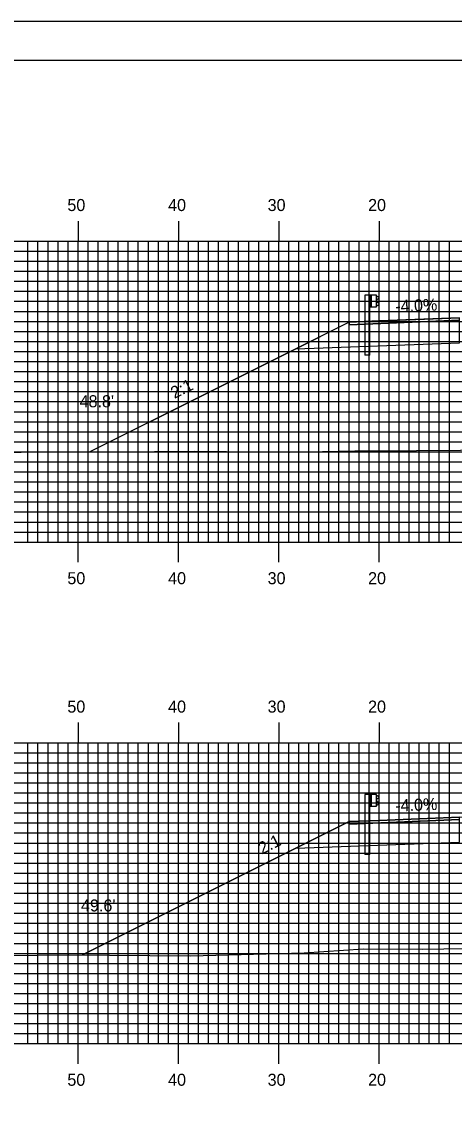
# Model space of a CAD drawing. Extents: x 1761004 to 1761347, y 442591 to 442811.
# Drawn here: x 1761114.1 to 1761157.2, y 442702.5 to 442810.5 of the extents above; entities that cross this region are included whole.
import ezdxf

# ---------------------------------------------------------------- set-up
doc = ezdxf.new("R2010")
doc.units = 0
for name, color, linetype in [('ANNOTATION', 7, 'Continuous'), ('BORDER', 7, 'Continuous'), ('D_Guardrail_Beam_Lt', 7, 'Continuous'), ('D_Roadway_Centerline', 7, 'Continuous'), ('D_Roadway_Edge_Shoulder', 7, 'Continuous'), ('D_Roadway_SlopeLines', 7, 'Continuous'), ('D_Roadway_SubGrade', 7, 'Continuous'), ('D_Text_Standard', 7, 'Continuous'), ('H_V ANNOTATION', 7, 'Continuous'), ('MAJOR', 7, 'Continuous'), ('MINOR', 7, 'Continuous'), ('PLOT BOUNDARY', 7, 'Continuous'), ('S_Roadway_Centerline', 7, 'Continuous')]:
    doc.layers.add(name, color=color, linetype=linetype)

msp = doc.modelspace()

# ---------------------------------------------------------------- linework, layer by layer
at = {"layer": 'BORDER'}
msp.add_lwpolyline([(1761020.13, 442596.67), (1761340.13, 442596.67), (1761340.13, 442806.67), (1761020.13, 442806.67)], close=True, dxfattribs=at)
at = {"layer": 'D_Guardrail_Beam_Lt'}
for p, q in [((1761148.3, 442783.3), (1761148.3, 442777.3)), ((1761148.77, 442783.3), (1761148.3, 442783.3)), ((1761149.46, 442783.3), (1761148.77, 442783.3)), ((1761148.77, 442783.3), (1761148.77, 442782.13)), ((1761148.83, 442783.3), (1761148.83, 442782.13)), ((1761148.94, 442783.3), (1761148.94, 442782.13)), ((1761149.46, 442782.13), (1761149.46, 442783.3)), ((1761149.46, 442783.21), (1761149.53, 442783.2)), ((1761149.46, 442782.75), (1761149.46, 442782.68)), ((1761149.69, 442782.95), (1761149.49, 442782.81)), ((1761149.49, 442782.61), (1761149.69, 442782.48)), ((1761149.55, 442783.19), (1761149.69, 442783.09)), ((1761148.77, 442782.13), (1761149.46, 442782.13)), ((1761148.79, 442777.3), (1761148.79, 442782.13)), ((1761149.53, 442782.23), (1761149.46, 442782.21)), ((1761149.69, 442782.33), (1761149.55, 442782.23)), ((1761148.79, 442777.3), (1761148.3, 442777.3)), ((1761148.3, 442733.52), (1761148.3, 442727.52)), ((1761148.77, 442733.52), (1761148.3, 442733.52)), ((1761149.46, 442733.52), (1761148.77, 442733.52)), ((1761148.77, 442733.52), (1761148.77, 442732.35)), ((1761148.83, 442733.52), (1761148.83, 442732.35)), ((1761148.94, 442733.52), (1761148.94, 442732.35)), ((1761149.46, 442732.35), (1761149.46, 442733.52)), ((1761149.46, 442733.43), (1761149.53, 442733.42)), ((1761149.46, 442732.97), (1761149.46, 442732.9)), ((1761149.69, 442733.17), (1761149.49, 442733.03)), ((1761149.49, 442732.83), (1761149.69, 442732.7)), ((1761149.55, 442733.41), (1761149.69, 442733.31)), ((1761148.77, 442732.35), (1761149.46, 442732.35)), ((1761148.79, 442727.52), (1761148.79, 442732.35)), ((1761149.53, 442732.45), (1761149.46, 442732.43)), ((1761149.69, 442732.55), (1761149.55, 442732.45)), ((1761148.79, 442727.52), (1761148.3, 442727.52))]:
    msp.add_line(p, q, dxfattribs=at)
for centre, major_axis, start_param, end_param in [((1761149.54, 442782.75), (-0.0789, 0), 5.323254, 6.283185), ((1761149.54, 442782.68), (-0.0789, 0), 6.283185, 7.243116), ((1761149.52, 442783.16), (0.0417, 0), 0.959931, 1.376053), ((1761149.64, 442783.02), (0.0877, 0), 5.323254, 7.243116), ((1761149.52, 442782.27), (0.0417, 0), 4.907132, 5.323254), ((1761149.64, 442782.41), (0.0877, 0), 5.323254, 7.243116), ((1761149.54, 442732.97), (-0.0789, 0), 5.323254, 6.283185), ((1761149.54, 442732.9), (-0.0789, 0), 6.283185, 7.243116), ((1761149.52, 442733.38), (0.0417, 0), 0.959931, 1.376053), ((1761149.64, 442733.24), (0.0877, 0), 5.323254, 7.243116), ((1761149.52, 442732.49), (0.0417, 0), 4.907132, 5.323254), ((1761149.64, 442732.63), (0.0877, 0), 5.323254, 7.243116)]:
    msp.add_ellipse(centre, major_axis=major_axis, ratio=0.995501, start_param=start_param, end_param=end_param, dxfattribs=at)
at = {"layer": 'D_Roadway_Centerline'}
for points in [[(1761120.9, 442767.68), (1761120.94, 442767.7), (1761132.33, 442773.39), (1761141.43, 442777.94), (1761141.43, 442777.95), (1761141.44, 442777.95), (1761146.45, 442780.45), (1761146.73, 442780.59), (1761149.73, 442780.71), (1761153.4, 442780.86), (1761157.73, 442781.03)], [(1761120.16, 442717.53), (1761133.13, 442724.02), (1761141.43, 442728.17), (1761146.73, 442730.81), (1761146.74, 442730.81), (1761149.72, 442730.93), (1761149.73, 442730.93), (1761157.72, 442731.25), (1761157.73, 442731.25), (1761166.12, 442731.56), (1761169.73, 442731.69), (1761175.62, 442731.9), (1761181.72, 442732.12), (1761181.73, 442732.12), (1761181.73, 442732.12), (1761185.69, 442731.96), (1761189.73, 442731.8), (1761192.73, 442731.68), (1761196.28, 442729.9), (1761197.48, 442729.3), (1761197.48, 442729.3), (1761202.44, 442726.82), (1761219.6, 442718.24)]]:
    msp.add_lwpolyline(points, dxfattribs=at)
at = {"layer": 'D_Roadway_Edge_Shoulder'}
for points in [[(1761157.73, 442781.03), (1761149.73, 442780.71), (1761149.73, 442780.71), (1761146.73, 442780.59), (1761146.73, 442780.34), (1761157.73, 442780.78)], [(1761157.73, 442731.25), (1761149.73, 442730.93), (1761149.73, 442730.93), (1761146.73, 442730.81), (1761146.73, 442730.56), (1761157.73, 442731)]]:
    msp.add_lwpolyline(points, close=True, dxfattribs=at)
at = {"layer": 'D_Roadway_SlopeLines'}
for points in [[(1761146.73, 442780.59), (1761120.9, 442767.68)], [(1761146.73, 442730.81), (1761120.16, 442717.53)]]:
    msp.add_lwpolyline(points, dxfattribs=at)
at = {"layer": 'D_Roadway_SubGrade'}
for points in [[(1761157.73, 442780.37), (1761157.73, 442780.78), (1761146.73, 442780.34), (1761146.73, 442780.59), (1761141.43, 442777.95), (1761157.73, 442778.53)], [(1761157.73, 442730.59), (1761157.73, 442731), (1761146.73, 442730.56), (1761146.73, 442730.81), (1761141.43, 442728.17), (1761157.73, 442728.75)]]:
    msp.add_lwpolyline(points, close=True, dxfattribs=at)
at = {"layer": 'MAJOR'}
for p, q in [((1761119.73, 442790.67), (1761119.73, 442788.67)), ((1761129.73, 442790.67), (1761129.73, 442788.67)), ((1761139.73, 442790.67), (1761139.73, 442788.67)), ((1761149.73, 442790.67), (1761149.73, 442788.67)), ((1761029.73, 442788.67), (1761309.73, 442788.67)), ((1761029.73, 442788.67), (1761309.73, 442788.67)), ((1761119.73, 442758.67), (1761119.73, 442788.67)), ((1761129.73, 442758.67), (1761129.73, 442788.67)), ((1761139.73, 442758.67), (1761139.73, 442788.67)), ((1761149.73, 442758.67), (1761149.73, 442788.67)), ((1761029.73, 442783.67), (1761309.73, 442783.67)), ((1761029.73, 442778.67), (1761309.73, 442778.67)), ((1761029.73, 442773.67), (1761309.73, 442773.67)), ((1761029.73, 442768.67), (1761309.73, 442768.67)), ((1761029.73, 442763.67), (1761309.73, 442763.67)), ((1761029.73, 442758.67), (1761309.73, 442758.67)), ((1761029.73, 442758.67), (1761309.73, 442758.67)), ((1761119.73, 442756.66), (1761119.73, 442758.67)), ((1761129.73, 442756.66), (1761129.73, 442758.67)), ((1761139.73, 442756.66), (1761139.73, 442758.67)), ((1761149.73, 442756.66), (1761149.73, 442758.67)), ((1761119.73, 442740.67), (1761119.73, 442738.67)), ((1761129.73, 442740.67), (1761129.73, 442738.67)), ((1761139.73, 442740.67), (1761139.73, 442738.67)), ((1761149.73, 442740.67), (1761149.73, 442738.67)), ((1761029.73, 442738.67), (1761309.73, 442738.67)), ((1761029.73, 442738.67), (1761309.73, 442738.67)), ((1761119.73, 442708.67), (1761119.73, 442738.67)), ((1761129.73, 442708.67), (1761129.73, 442738.67)), ((1761139.73, 442708.67), (1761139.73, 442738.67)), ((1761149.73, 442708.67), (1761149.73, 442738.67)), ((1761029.73, 442733.67), (1761309.73, 442733.67)), ((1761029.73, 442728.67), (1761309.73, 442728.67)), ((1761029.73, 442723.67), (1761309.73, 442723.67)), ((1761029.73, 442718.67), (1761309.73, 442718.67)), ((1761029.73, 442713.67), (1761309.73, 442713.67)), ((1761029.73, 442708.67), (1761309.73, 442708.67)), ((1761029.73, 442708.67), (1761309.73, 442708.67)), ((1761119.73, 442706.66), (1761119.73, 442708.67)), ((1761129.73, 442706.66), (1761129.73, 442708.67)), ((1761139.73, 442706.66), (1761139.73, 442708.67)), ((1761149.73, 442706.66), (1761149.73, 442708.67))]:
    msp.add_line(p, q, dxfattribs=at)
at = {"layer": 'MINOR'}
for p, q in [((1761114.73, 442758.67), (1761114.73, 442788.67)), ((1761115.73, 442758.67), (1761115.73, 442788.67)), ((1761116.73, 442758.67), (1761116.73, 442788.67)), ((1761117.73, 442758.67), (1761117.73, 442788.67)), ((1761118.73, 442758.67), (1761118.73, 442788.67)), ((1761120.73, 442758.67), (1761120.73, 442788.67)), ((1761121.73, 442758.67), (1761121.73, 442788.67)), ((1761122.73, 442758.67), (1761122.73, 442788.67)), ((1761123.73, 442758.67), (1761123.73, 442788.67)), ((1761124.73, 442758.67), (1761124.73, 442788.67)), ((1761125.73, 442758.67), (1761125.73, 442788.67)), ((1761126.73, 442758.67), (1761126.73, 442788.67)), ((1761127.73, 442758.67), (1761127.73, 442788.67)), ((1761128.73, 442758.67), (1761128.73, 442788.67)), ((1761130.73, 442758.67), (1761130.73, 442788.67)), ((1761131.73, 442758.67), (1761131.73, 442788.67)), ((1761132.73, 442758.67), (1761132.73, 442788.67)), ((1761133.73, 442758.67), (1761133.73, 442788.67)), ((1761134.73, 442758.67), (1761134.73, 442788.67)), ((1761135.73, 442758.67), (1761135.73, 442788.67)), ((1761136.73, 442758.67), (1761136.73, 442788.67)), ((1761137.73, 442758.67), (1761137.73, 442788.67)), ((1761138.73, 442758.67), (1761138.73, 442788.67)), ((1761140.73, 442758.67), (1761140.73, 442788.67)), ((1761141.73, 442758.67), (1761141.73, 442788.67)), ((1761142.73, 442758.67), (1761142.73, 442788.67)), ((1761143.73, 442758.67), (1761143.73, 442788.67)), ((1761144.73, 442758.67), (1761144.73, 442788.67)), ((1761145.73, 442758.67), (1761145.73, 442788.67)), ((1761146.73, 442758.67), (1761146.73, 442788.67)), ((1761147.73, 442758.67), (1761147.73, 442788.67)), ((1761148.73, 442758.67), (1761148.73, 442788.67)), ((1761150.73, 442758.67), (1761150.73, 442788.67)), ((1761151.73, 442758.67), (1761151.73, 442788.67)), ((1761152.73, 442758.67), (1761152.73, 442788.67)), ((1761153.73, 442758.67), (1761153.73, 442788.67)), ((1761154.73, 442758.67), (1761154.73, 442788.67)), ((1761155.73, 442758.67), (1761155.73, 442788.67)), ((1761156.73, 442758.67), (1761156.73, 442788.67)), ((1761029.73, 442787.67), (1761309.73, 442787.67)), ((1761029.73, 442786.67), (1761309.73, 442786.67)), ((1761029.73, 442785.67), (1761309.73, 442785.67)), ((1761029.73, 442784.67), (1761309.73, 442784.67)), ((1761029.73, 442782.67), (1761309.73, 442782.67)), ((1761029.73, 442781.67), (1761309.73, 442781.67)), ((1761029.73, 442780.67), (1761309.73, 442780.67)), ((1761029.73, 442779.67), (1761309.73, 442779.67)), ((1761029.73, 442777.67), (1761309.73, 442777.67)), ((1761029.73, 442776.67), (1761309.73, 442776.67)), ((1761029.73, 442775.67), (1761309.73, 442775.67)), ((1761029.73, 442774.67), (1761309.73, 442774.67)), ((1761029.73, 442772.67), (1761309.73, 442772.67)), ((1761029.73, 442771.67), (1761309.73, 442771.67)), ((1761029.73, 442770.67), (1761309.73, 442770.67)), ((1761029.73, 442769.67), (1761309.73, 442769.67)), ((1761029.73, 442767.67), (1761309.73, 442767.67)), ((1761029.73, 442766.67), (1761309.73, 442766.67)), ((1761029.73, 442765.67), (1761309.73, 442765.67)), ((1761029.73, 442764.67), (1761309.73, 442764.67)), ((1761029.73, 442762.67), (1761309.73, 442762.67)), ((1761029.73, 442761.67), (1761309.73, 442761.67)), ((1761029.73, 442760.67), (1761309.73, 442760.67)), ((1761029.73, 442759.67), (1761309.73, 442759.67)), ((1761114.73, 442708.67), (1761114.73, 442738.67)), ((1761115.73, 442708.67), (1761115.73, 442738.67)), ((1761116.73, 442708.67), (1761116.73, 442738.67)), ((1761117.73, 442708.67), (1761117.73, 442738.67)), ((1761118.73, 442708.67), (1761118.73, 442738.67)), ((1761120.73, 442708.67), (1761120.73, 442738.67)), ((1761121.73, 442708.67), (1761121.73, 442738.67)), ((1761122.73, 442708.67), (1761122.73, 442738.67)), ((1761123.73, 442708.67), (1761123.73, 442738.67)), ((1761124.73, 442708.67), (1761124.73, 442738.67)), ((1761125.73, 442708.67), (1761125.73, 442738.67)), ((1761126.73, 442708.67), (1761126.73, 442738.67)), ((1761127.73, 442708.67), (1761127.73, 442738.67)), ((1761128.73, 442708.67), (1761128.73, 442738.67)), ((1761130.73, 442708.67), (1761130.73, 442738.67)), ((1761131.73, 442708.67), (1761131.73, 442738.67)), ((1761132.73, 442708.67), (1761132.73, 442738.67)), ((1761133.73, 442708.67), (1761133.73, 442738.67)), ((1761134.73, 442708.67), (1761134.73, 442738.67)), ((1761135.73, 442708.67), (1761135.73, 442738.67)), ((1761136.73, 442708.67), (1761136.73, 442738.67)), ((1761137.73, 442708.67), (1761137.73, 442738.67)), ((1761138.73, 442708.67), (1761138.73, 442738.67)), ((1761140.73, 442708.67), (1761140.73, 442738.67)), ((1761141.73, 442708.67), (1761141.73, 442738.67)), ((1761142.73, 442708.67), (1761142.73, 442738.67)), ((1761143.73, 442708.67), (1761143.73, 442738.67)), ((1761144.73, 442708.67), (1761144.73, 442738.67)), ((1761145.73, 442708.67), (1761145.73, 442738.67)), ((1761146.73, 442708.67), (1761146.73, 442738.67)), ((1761147.73, 442708.67), (1761147.73, 442738.67)), ((1761148.73, 442708.67), (1761148.73, 442738.67)), ((1761150.73, 442708.67), (1761150.73, 442738.67)), ((1761151.73, 442708.67), (1761151.73, 442738.67)), ((1761152.73, 442708.67), (1761152.73, 442738.67)), ((1761153.73, 442708.67), (1761153.73, 442738.67)), ((1761154.73, 442708.67), (1761154.73, 442738.67)), ((1761155.73, 442708.67), (1761155.73, 442738.67)), ((1761156.73, 442708.67), (1761156.73, 442738.67)), ((1761029.73, 442737.67), (1761309.73, 442737.67)), ((1761029.73, 442736.67), (1761309.73, 442736.67)), ((1761029.73, 442735.67), (1761309.73, 442735.67)), ((1761029.73, 442734.67), (1761309.73, 442734.67)), ((1761029.73, 442732.67), (1761309.73, 442732.67)), ((1761029.73, 442731.67), (1761309.73, 442731.67)), ((1761029.73, 442730.67), (1761309.73, 442730.67)), ((1761029.73, 442729.67), (1761309.73, 442729.67)), ((1761029.73, 442727.67), (1761309.73, 442727.67)), ((1761029.73, 442726.67), (1761309.73, 442726.67)), ((1761029.73, 442725.67), (1761309.73, 442725.67)), ((1761029.73, 442724.67), (1761309.73, 442724.67)), ((1761029.73, 442722.67), (1761309.73, 442722.67)), ((1761029.73, 442721.67), (1761309.73, 442721.67)), ((1761029.73, 442720.67), (1761309.73, 442720.67)), ((1761029.73, 442719.67), (1761309.73, 442719.67)), ((1761029.73, 442717.67), (1761309.73, 442717.67)), ((1761029.73, 442716.67), (1761309.73, 442716.67)), ((1761029.73, 442715.67), (1761309.73, 442715.67)), ((1761029.73, 442714.67), (1761309.73, 442714.67)), ((1761029.73, 442712.67), (1761309.73, 442712.67)), ((1761029.73, 442711.67), (1761309.73, 442711.67)), ((1761029.73, 442710.67), (1761309.73, 442710.67)), ((1761029.73, 442709.67), (1761309.73, 442709.67))]:
    msp.add_line(p, q, dxfattribs=at)
at = {"layer": 'PLOT BOUNDARY'}
msp.add_lwpolyline([(1761003.94, 442590.55), (1761343.94, 442590.55), (1761343.94, 442810.55), (1761003.94, 442810.55)], close=True, dxfattribs=at)
at = {"layer": 'S_Roadway_Centerline'}
for points in [[(1761109.02, 442767.52), (1761115.76, 442767.67), (1761123.28, 442767.68), (1761131.38, 442767.72), (1761140.83, 442767.63), (1761147.32, 442767.75), (1761153.45, 442767.79), (1761162.23, 442767.86), (1761171.78, 442767.82), (1761176.21, 442767.8), (1761185.96, 442767.92), (1761197.12, 442767.78), (1761197.8, 442767.78), (1761198.51, 442767.77), (1761207.32, 442767.48), (1761219.46, 442767.1), (1761220.4, 442767.06), (1761221.43, 442767.02), (1761232.1, 442766.5)], [(1761109.37, 442717.44), (1761118.81, 442717.54), (1761130.94, 442717.43), (1761142.25, 442717.71), (1761148.13, 442718.11), (1761154.04, 442718.1), (1761160.42, 442718.19), (1761166.65, 442718.27), (1761174.9, 442718.53), (1761177, 442718.57), (1761190.8, 442718.67), (1761195.27, 442718.63), (1761199.34, 442718.52), (1761214.85, 442718.21), (1761216.92, 442718.28), (1761221.47, 442718.21), (1761237.8, 442717.59)]]:
    msp.add_lwpolyline(points, dxfattribs=at)

# ---------------------------------------------------------------- texts
at = {"layer": 'ANNOTATION'}
for s, rotation, p in [('-4.0%', 2.2908, (1761151.36, 442781.58)), ('2:1', 26.5667, (1761129.33, 442772.93)), ('-4.0%', 2.2906, (1761151.36, 442731.8)), ('2:1', 26.5665, (1761138.07, 442727.52))]:
    msp.add_text(s, height=1.2, rotation=rotation, dxfattribs=at).set_placement(p)
at = {"layer": 'D_Text_Standard'}
for s, p in [("48.8'", (1761119.88, 442772.11)), ("49.6'", (1761120.02, 442721.85))]:
    msp.add_text(s, height=1.2, dxfattribs=at).set_placement(p)
at = {"layer": 'H_V ANNOTATION'}
for s, p in [('50', (1761118.66, 442791.67)), ('40', (1761128.7, 442791.67)), ('30', (1761138.62, 442791.67)), ('20', (1761148.63, 442791.67)), ('50', (1761118.66, 442754.47)), ('40', (1761128.7, 442754.47)), ('30', (1761138.62, 442754.47)), ('20', (1761148.63, 442754.47)), ('50', (1761118.66, 442741.67)), ('40', (1761128.7, 442741.67)), ('30', (1761138.62, 442741.67)), ('20', (1761148.63, 442741.67)), ('50', (1761118.66, 442704.47)), ('40', (1761128.7, 442704.47)), ('30', (1761138.62, 442704.47)), ('20', (1761148.63, 442704.47))]:
    msp.add_text(s, height=1.2, dxfattribs=at).set_placement(p)

doc.saveas('drawing.dxf')
